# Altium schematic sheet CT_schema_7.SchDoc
size 254 x 194 mm
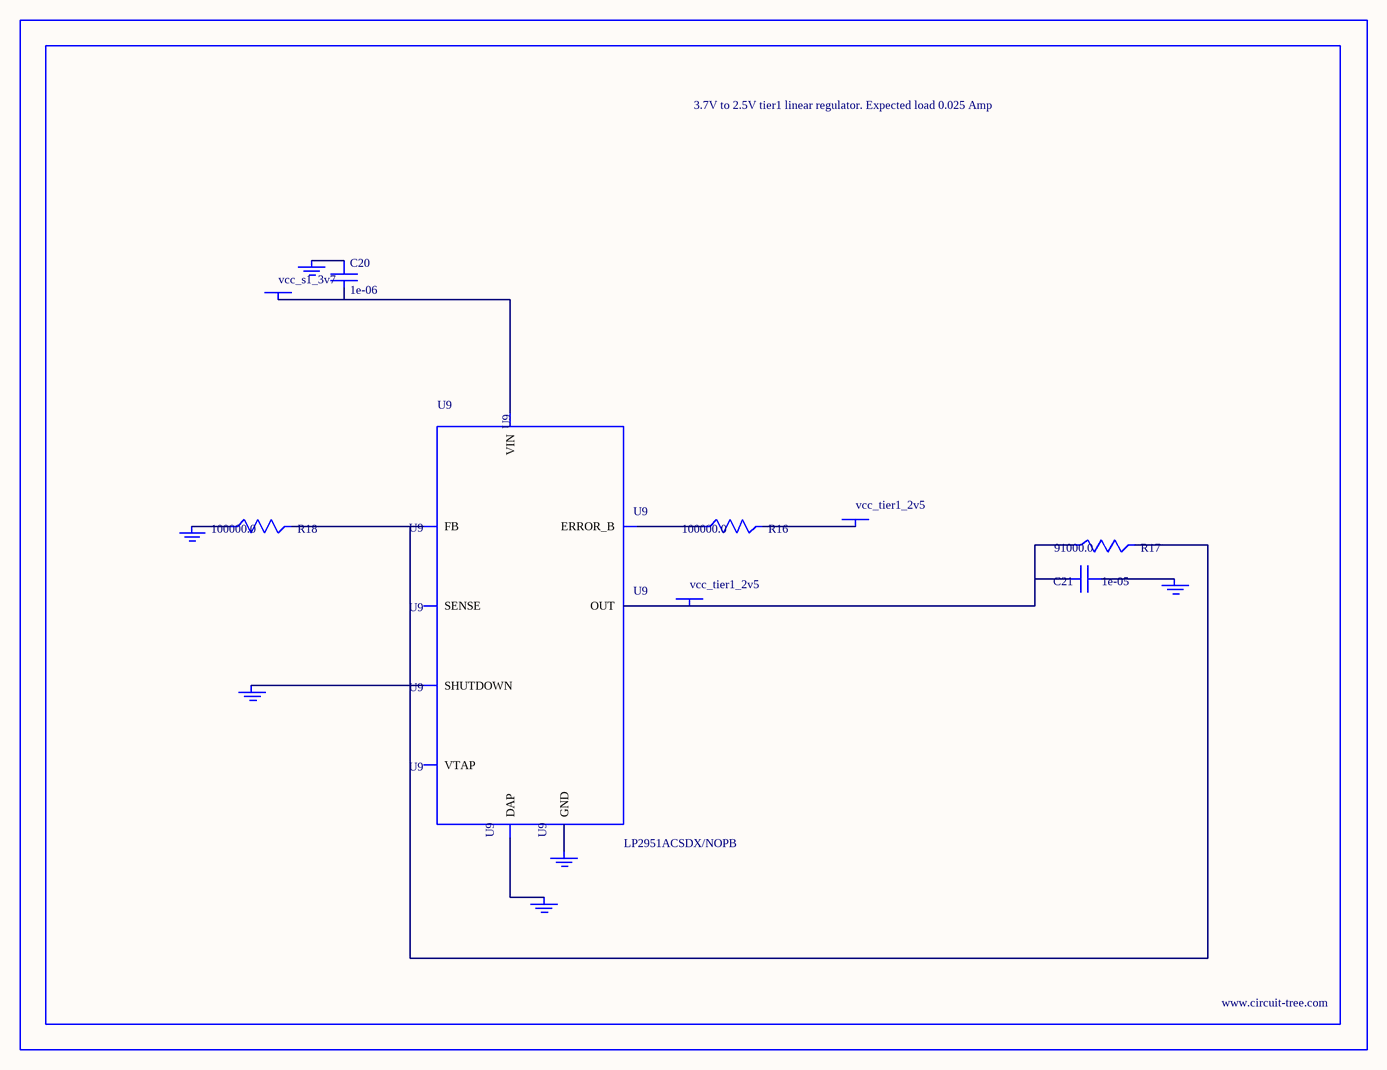
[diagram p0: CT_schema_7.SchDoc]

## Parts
BORDER6  (no value)
C20  1e-06  [C0603]
C21  1e-05  [C1210]
GND_INSTANCE_6_0  (no value)
GND_INSTANCE_6_1  (no value)
GND_INSTANCE_6_2  (no value)
GND_INSTANCE_6_3  (no value)
GND_INSTANCE_6_4  (no value)
GND_INSTANCE_6_5  (no value)
POWER_INSTANCE_6_0  vcc_tier1_2v5
POWER_INSTANCE_6_1  vcc_s1_3v7
POWER_INSTANCE_6_2  vcc_tier1_2v5
R16  100000.0  [R0603]
R17  91000.0  [R0603]
R18  100000.0  [R0603]
U9  LP2951ACSDX/NOPB  [WSON-8]

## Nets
NetC20_1: C20.1 GND_INSTANCE_6_3.0(GND)
NetC20_2: C20.2 POWER_INSTANCE_6_1.0(PWR) U9.8(VIN)
NetC21_1: C21.1 GND_INSTANCE_6_0.0(GND)
NetC21_2: C21.2 POWER_INSTANCE_6_2.0(PWR) R17.1 U9.1(OUT)
NetGND_INSTANCE_6_1_0: GND_INSTANCE_6_1.0(GND) U9.3(SHUTDOWN)
NetGND_INSTANCE_6_2_0: GND_INSTANCE_6_2.0(GND) R18.1
NetGND_INSTANCE_6_4_0: GND_INSTANCE_6_4.0(GND) U9.PAD(DAP)
NetGND_INSTANCE_6_5_0: GND_INSTANCE_6_5.0(GND) U9.4(GND)
NetPOWER_INSTANCE_6_0_0: POWER_INSTANCE_6_0.0(PWR) R16.2
NetR16_1: R16.1 U9.5(ERROR_B)
NetR17_2: R17.2 R18.2 U9.7(FB)

Not connected (* = marked no-connect by the designer): U9 2(SENSE) 6(VTAP)

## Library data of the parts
BORDER6 = BORDER_PAGE6
C20 = C0603C105K3RACTU
C21 = GRM32DR61E106MA12L
GND_INSTANCE_6_0-GND_INSTANCE_6_5 = GND
POWER_INSTANCE_6_0-POWER_INSTANCE_6_2 = PWR
R16 R18 = RC0603JR-07100KL
R17 = RC0603JR-0791KL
